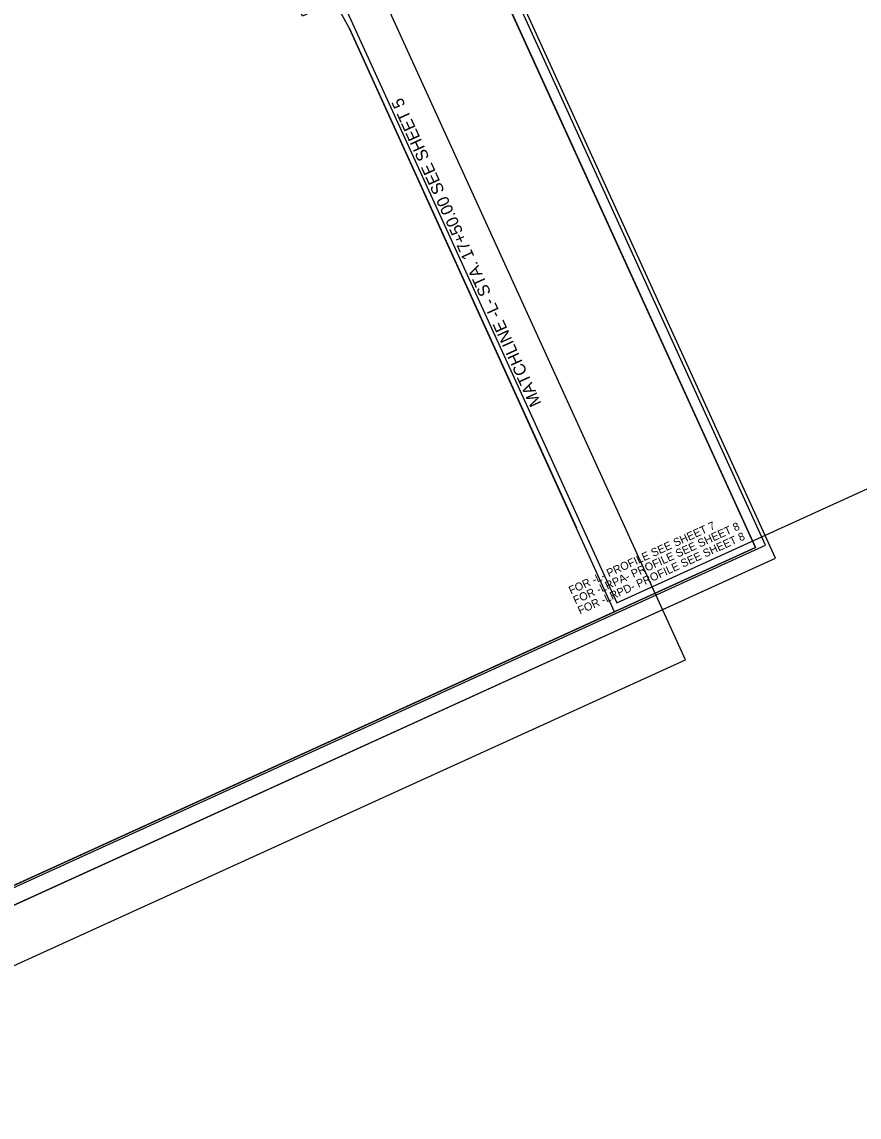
# Model space of a CAD drawing. Extents: x 2246788 to 2250969, y 662010 to 664598.
# Drawn here: x 2247833 to 2248878, y 662010 to 663378 of the extents above; entities that cross this region are included whole.
import ezdxf

# ---------------------------------------------------------------- set-up
doc = ezdxf.new("R2010")
doc.units = 0
for name, color, linetype in [('Matchline', 7, 'Continuous'), ('Matchline Text', 7, 'Continuous'), ('Prop Dimension', 7, 'Continuous'), ('Sheet Clip Boundary CELL', 7, 'Continuous'), ('Sheet Cutting Line CELL', 7, 'Continuous'), ('Sheet Layout Plan Border', 7, 'Continuous'), ('Sheet Plan CELL', 7, 'Continuous'), ('Sheet Plan Layout CELL', 7, 'Continuous'), ('Sheet Plot Border Inside CELL', 7, 'Continuous'), ('Sheet Plot Border Outside CELL', 7, 'Continuous')]:
    doc.layers.add(name, color=color, linetype=linetype)

msp = doc.modelspace()

# ---------------------------------------------------------------- linework, layer by layer
at = {"layer": 'Matchline'}
msp.add_line((2248241.7, 663371.1), (2248525.4, 662746.4), dxfattribs=at)
at = {"layer": 'Sheet Clip Boundary CELL'}
msp.add_lwpolyline([(2248573, 662641.6), (2248489.8, 662824.8), (2248241.7, 663371.1), (2248193.9, 663457.8), (2248131.6, 663594.3), (2247008.7, 663082.6), (2247444.4, 662127.3)], close=True, dxfattribs=at)
at = {"layer": 'Sheet Cutting Line CELL'}
msp.add_line((2247241.9, 662010.3), (2248773.9, 662708.4), dxfattribs=at)
at = {"layer": 'Sheet Layout Plan Border'}
for points in [[(2248198.1, 663481.5), (2248575.8, 662652.8), (2249849.7, 663233.3), (2249502.1, 663996.3), (2249329.8, 663917.8), (2249242.1, 664110.3), (2248140.4, 663608.2)], [(2248661.4, 662581.6), (2248242.8, 663500.1), (2248080.9, 663855.5), (2247317.9, 663507.9), (2247396.3, 663335.6), (2247203.9, 663247.9), (2247705.9, 662146.2)]]:
    msp.add_lwpolyline(points, close=True, dxfattribs=at)
at = {"layer": 'Sheet Plan CELL'}
for points in [[(2248313.7, 663677.3), (2246948.7, 663055.3), (2247384.1, 662099.8), (2248749.1, 662721.8)], [(2247384.1, 662099.8), (2246948.7, 663055.2), (2248131.6, 663594.3), (2248193.9, 663457.8), (2248375.9, 663540.7), (2248749.1, 662721.8)]]:
    msp.add_lwpolyline(points, close=True, dxfattribs=at)
at = {"layer": 'Sheet Plan Layout CELL'}
msp.add_lwpolyline([(2246948.7, 663055.2), (2247384.1, 662099.8), (2248749, 662721.8), (2248401.3, 663484.8), (2248183.6, 663385.6), (2248095.9, 663578.1)], close=True, dxfattribs=at)
at = {"layer": 'Sheet Plot Border Inside CELL'}
msp.add_lwpolyline([(2247245.5, 662033.9), (2248761.5, 662724.7), (2248324, 663684.7), (2246808, 662993.9)], close=True, dxfattribs=at)
at = {"layer": 'Sheet Plot Border Outside CELL'}
msp.add_lwpolyline([(2247241.9, 662010.3), (2248773.9, 662708.4), (2248319.8, 663704.8), (2246787.9, 663006.7)], close=True, dxfattribs=at)

# ---------------------------------------------------------------- texts
at = {"layer": 'Matchline Text'}
msp.add_text('MATCHLINE -L- STA. 17+50.00 SEE SHEET 5', height=15, rotation=114.4979, dxfattribs=at).set_placement((2248482, 662901.8))
at = {"layer": 'Prop Dimension'}
for s, p in [('FOR -L- PROFILE SEE SHEET 7', (2248518.5, 662663)), ('FOR -LRPA- PROFILE SEE SHEET 8', (2248524.1, 662650.8)), ('FOR -LRPD- PROFILE SEE SHEET 8', (2248529.9, 662638))]:
    msp.add_text(s, height=10, rotation=24.4979, dxfattribs=at).set_placement(p)

doc.saveas('drawing.dxf')
